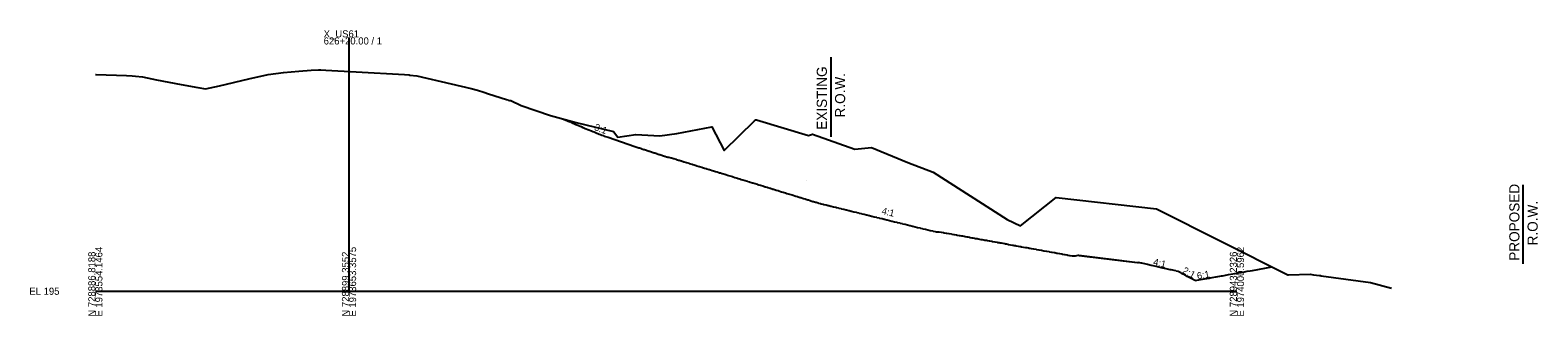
# Model space of a CAD drawing. Extents: x -26 to 630, y -39 to 9098.
# Drawn here: x -26 to 569, y 5490 to 5603 of the extents above; entities that cross this region are included whole.
import ezdxf

# ---------------------------------------------------------------- set-up
doc = ezdxf.new("R2010")
doc.units = 0
for name, color, linetype in [('CONST_DCH', 7, 'Continuous'), ('Default', 7, 'Continuous'), ('Draft_XS_Grid', 7, 'Continuous'), ('DTM_X_GROUND', 7, 'Continuous'), ('X_DTM_CONTOURS_MAJOR', 7, 'Continuous'), ('XS_CELL', 7, 'Continuous'), ('XS_P_GROUND', 7, 'Continuous'), ('XS_P_ROW', 7, 'Continuous'), ('XS_P_TX_FS_BS', 7, 'Continuous'), ('XS_X_ROW', 7, 'Continuous')]:
    doc.layers.add(name, color=color, linetype=linetype)

msp = doc.modelspace()

# ---------------------------------------------------------------- linework, layer by layer
at = {"layer": 'DTM_X_GROUND'}
msp.add_lwpolyline([(0, 5585.34), (0.34, 5585.34), (12.35, 5584.96), (14.49, 5584.89), (15.87, 5584.73), (18.56, 5584.42), (24.13, 5583.26), (33.77, 5581.44), (40.42, 5580.22), (43.38, 5579.67), (48.92, 5580.95), (60.54, 5583.64), (68.12, 5585.37), (74.21, 5586.16), (80.16, 5586.65), (85.13, 5587.07), (88.03, 5587.19), (88.84, 5587.22), (90.85, 5587.11), (102.76, 5586.44), (121.82, 5585.33), (123.66, 5585.22), (124.01, 5585.18), (126.77, 5584.86), (140.24, 5581.65), (148.09, 5579.88), (150.61, 5579.18), (153.19, 5578.38), (154.95, 5577.81), (162.05, 5575.51), (162.54, 5575.34), (162.79, 5575.25), (163.32, 5575.16), (163.78, 5575.08), (167.92, 5573.21), (179.48, 5569.21), (189.49, 5566.5), (204.19, 5562.87), (206.01, 5560.69), (213.03, 5561.75), (222.57, 5561.26), (229.25, 5562.07), (243, 5564.77), (247.82, 5555.49), (259.81, 5567.15), (260.33, 5567.54), (260.56, 5567.55), (281.09, 5561.3), (282.71, 5561.82), (299.36, 5555.96), (305.98, 5556.65), (320.29, 5550.74), (330.27, 5546.87), (359.43, 5528.31), (364.69, 5525.82), (378.69, 5536.89), (418.26, 5532.46), (470.05, 5506.4), (470.34, 5506.47), (478.82, 5506.66), (480.12, 5506.51), (482.61, 5506.17), (482.94, 5506.13), (483.15, 5506.1), (502.67, 5503.47), (510.96, 5501.18)], dxfattribs=at)
at = {"layer": 'XS_CELL'}
for p, q in [((100, 5500), (100, 5600)), ((0, 5500), (100, 5500)), ((100, 5500), (450, 5500))]:
    msp.add_line(p, q, dxfattribs=at)
at = {"layer": 'XS_P_GROUND'}
for points in [[(184.19, 5567.94), (185.14, 5567.53), (185.19, 5567.51), (186.14, 5567.11), (186.38, 5567), (187.14, 5566.68), (187.62, 5566.47), (187.74, 5566.42), (188.14, 5566.25), (188.35, 5566.16), (189.14, 5565.83), (189.39, 5565.72), (190.14, 5565.4), (190.43, 5565.28), (191.14, 5564.97), (191.47, 5564.83), (192.14, 5564.55), (192.5, 5564.4), (193.14, 5564.14), (193.53, 5563.98), (194.14, 5563.73), (194.56, 5563.56), (195.14, 5563.33), (195.58, 5563.15), (196.14, 5562.92), (196.6, 5562.73), (197.14, 5562.51), (197.62, 5562.31), (198.14, 5562.11), (198.64, 5561.9), (199.14, 5561.7), (199.65, 5561.49), (200.14, 5561.29), (200.61, 5561.15), (201.14, 5560.98), (201.6, 5560.84), (202.14, 5560.68), (212.72, 5557.04)], [(212.72, 5557.04), (213.47, 5556.79), (214.22, 5556.55), (214.48, 5556.46), (215.23, 5556.21), (215.48, 5556.13), (216.25, 5555.88), (216.49, 5555.8), (217.26, 5555.55), (217.49, 5555.48), (218.27, 5555.22), (218.49, 5555.15), (219.28, 5554.89), (219.5, 5554.82), (220.29, 5554.56), (220.5, 5554.49), (221.3, 5554.23), (221.5, 5554.16), (222.31, 5553.9), (222.51, 5553.83), (223.32, 5553.57), (223.51, 5553.51), (224.33, 5553.24), (224.51, 5553.18), (225.2, 5552.95), (225.34, 5552.91), (225.65, 5552.86), (226.09, 5552.84), (226.93, 5552.58), (227.09, 5552.53), (227.93, 5552.28), (228.09, 5552.23), (228.94, 5551.97), (229.09, 5551.92), (229.94, 5551.66), (230.09, 5551.61), (230.95, 5551.35), (231.09, 5551.31), (231.99, 5551.03), (232.09, 5551), (233.02, 5550.71), (233.09, 5550.69), (234.05, 5550.4), (234.09, 5550.38), (235.09, 5550.08), (235.09, 5550.08), (235.24, 5550.03), (235.29, 5550.02), (235.5, 5549.95), (236.09, 5549.77), (236.78, 5549.56), (237.09, 5549.46), (238.07, 5549.16), (238.09, 5549.16), (238.19, 5549.13), (239.09, 5548.85), (239.35, 5548.77), (240.09, 5548.54), (240.63, 5548.38), (240.7, 5548.36), (240.74, 5548.35), (241.09, 5548.23), (241.9, 5547.99), (242.09, 5547.93), (242.54, 5547.79), (243.09, 5547.62), (243.7, 5547.43), (244.1, 5547.31), (244.46, 5547.2), (245.1, 5547.01), (245.8, 5546.79), (246.1, 5546.7), (246.37, 5546.61), (247.1, 5546.39), (247.65, 5546.22), (248.1, 5546.08), (248.92, 5545.83), (249.1, 5545.78), (249.56, 5545.64), (250.1, 5545.47), (250.7, 5545.29), (251.1, 5545.16), (251.47, 5545.05), (252.1, 5544.86), (252.1, 5544.85), (253.1, 5544.55), (253.37, 5544.46), (254.1, 5544.24), (254.64, 5544.07), (255.1, 5543.93), (255.28, 5543.88), (256.1, 5543.63), (257.01, 5543.35), (257.1, 5543.32), (257.18, 5543.3), (257.32, 5543.25), (257.81, 5543.1), (258.1, 5543.01), (259.08, 5542.71), (259.1, 5542.71), (259.12, 5542.7), (260.1, 5542.4), (260.98, 5542.13), (261.1, 5542.09), (261.57, 5541.95), (262.1, 5541.78), (262.24, 5541.74), (263.1, 5541.48), (264.06, 5541.18), (264.1, 5541.17), (264.14, 5541.16), (264.2, 5541.14), (264.77, 5540.97), (265.1, 5540.86), (266.03, 5540.58), (266.1, 5540.56), (266.11, 5540.55), (267.1, 5540.25), (267.26, 5540.2), (268.1, 5539.94), (268.36, 5539.86), (269.1, 5539.63), (269.45, 5539.53), (270.1, 5539.33), (270.52, 5539.2), (271.1, 5539.02), (271.57, 5538.88), (272.1, 5538.71), (272.62, 5538.55), (273.1, 5538.41), (273.66, 5538.24), (274.1, 5538.1), (274.69, 5537.92), (275.1, 5537.79), (275.72, 5537.6), (276.1, 5537.48), (276.75, 5537.29), (277.1, 5537.18), (277.77, 5536.97), (278.1, 5536.87), (278.79, 5536.66), (279.1, 5536.56), (279.81, 5536.35), (280.1, 5536.26), (280.82, 5536.04), (281.1, 5535.95), (281.84, 5535.72), (282.1, 5535.64), (282.85, 5535.41), (283.1, 5535.34), (283.86, 5535.1), (284.1, 5535.03), (284.87, 5534.79), (285.1, 5534.72), (285.89, 5534.53), (286.1, 5534.48), (286.89, 5534.28), (287.1, 5534.23), (287.9, 5534.03), (288.11, 5533.99), (288.91, 5533.79), (289.11, 5533.74), (289.92, 5533.54), (290.11, 5533.5), (290.93, 5533.29), (291.11, 5533.25), (291.93, 5533.05), (292.11, 5533), (292.94, 5532.8), (293.11, 5532.76), (293.95, 5532.55), (294.11, 5532.51), (294.95, 5532.31), (295.11, 5532.27), (295.96, 5532.06), (296.11, 5532.02), (296.96, 5531.81), (297.11, 5531.78), (297.97, 5531.57), (298.11, 5531.53), (298.97, 5531.32), (299.11, 5531.29), (299.98, 5531.08), (300.11, 5531.04), (300.98, 5530.83), (301.11, 5530.8), (301.98, 5530.58), (302.11, 5530.55), (302.99, 5530.34), (303.11, 5530.31), (303.99, 5530.09), (304.11, 5530.06), (305, 5529.85), (305.11, 5529.82), (306, 5529.6), (306.11, 5529.57), (307, 5529.35), (307.11, 5529.33), (308, 5529.11), (308.11, 5529.08), (309.01, 5528.86), (309.11, 5528.84), (310.01, 5528.62), (310.11, 5528.59), (311.01, 5528.37), (311.11, 5528.35), (312.02, 5528.13), (312.11, 5528.1), (313.02, 5527.88), (313.11, 5527.86), (314.02, 5527.63), (314.11, 5527.61), (315.02, 5527.39), (315.11, 5527.37), (316.03, 5527.14), (316.11, 5527.12), (316.2, 5527.1), (317.11, 5526.88), (317.2, 5526.86), (318.11, 5526.63), (318.2, 5526.61), (319.11, 5526.39), (319.2, 5526.36), (320.11, 5526.14), (320.2, 5526.12), (321.11, 5525.9), (321.21, 5525.87), (322.11, 5525.65), (322.21, 5525.63), (323.11, 5525.41), (323.21, 5525.38), (324.11, 5525.16), (324.21, 5525.14), (325.11, 5524.92), (325.22, 5524.89), (326.11, 5524.67), (326.22, 5524.64), (327.11, 5524.42), (327.22, 5524.41), (328.11, 5524.19), (328.22, 5524.18), (329.11, 5523.96), (329.23, 5523.94), (330.11, 5523.73), (330.23, 5523.71), (331.12, 5523.49), (331.14, 5523.49), (331.34, 5523.44), (331.7, 5523.41), (331.92, 5523.41), (332.29, 5523.4), (332.52, 5523.41), (332.68, 5523.4), (333.38, 5523.28), (333.54, 5523.25), (334.39, 5523.09), (334.57, 5523.06), (335.4, 5522.91), (335.59, 5522.88), (336.42, 5522.73), (336.62, 5522.69), (337.43, 5522.55), (337.65, 5522.51), (338.44, 5522.36), (338.68, 5522.32), (339.46, 5522.18), (339.71, 5522.13), (340.47, 5522), (340.75, 5521.95), (341.49, 5521.81), (341.78, 5521.76), (342.5, 5521.63), (342.82, 5521.57), (343.51, 5521.45), (343.86, 5521.38), (344.53, 5521.26), (344.9, 5521.2), (345.54, 5521.08), (345.95, 5521.01), (346.55, 5520.9), (347, 5520.82), (347.57, 5520.72), (348.05, 5520.63), (348.58, 5520.53), (349.11, 5520.44), (349.59, 5520.35), (350.18, 5520.24), (350.61, 5520.17), (351.25, 5520.05), (351.62, 5519.98), (352.34, 5519.85), (352.63, 5519.8), (353.44, 5519.66), (353.65, 5519.62), (354.55, 5519.46), (354.66, 5519.44), (355.58, 5519.27), (355.67, 5519.25), (356.32, 5519.14), (356.69, 5519.07), (357, 5519.01), (357.7, 5518.89), (358.53, 5518.74), (358.72, 5518.7), (359.11, 5518.63), (359.73, 5518.52), (360.01, 5518.47), (360.74, 5518.34), (361.48, 5518.2), (361.76, 5518.15), (362.22, 5518.07), (362.77, 5517.97), (362.96, 5517.94), (363.78, 5517.79), (364.43, 5517.67), (364.8, 5517.61), (365.1, 5517.55), (365.81, 5517.42), (366.64, 5517.27), (366.82, 5517.24), (367.22, 5517.17), (367.84, 5517.06), (368.12, 5517.01), (368.24, 5516.98), (368.43, 5516.95), (368.85, 5516.87), (368.86, 5516.87), (369.86, 5516.69), (369.91, 5516.68), (370.88, 5516.51), (370.95, 5516.5), (371.89, 5516.33), (371.99, 5516.31), (372.91, 5516.14), (373.02, 5516.12), (373.92, 5515.96), (374.06, 5515.93), (374.93, 5515.78), (375.1, 5515.75), (375.95, 5515.59), (376.13, 5515.56), (376.96, 5515.41), (377.17, 5515.37), (377.97, 5515.23), (378.2, 5515.19), (378.99, 5515.04), (379.23, 5515), (380, 5514.86), (380.25, 5514.82), (381.01, 5514.68), (381.27, 5514.63), (382.03, 5514.5), (382.28, 5514.45), (383.04, 5514.31), (383.3, 5514.27), (384.05, 5514.13), (384.3, 5514.09), (384.99, 5513.96), (386.18, 5513.9), (386.37, 5513.91), (387.38, 5514.14), (387.59, 5514.15), (387.92, 5514.11), (388.64, 5514.02), (388.99, 5513.98), (389.69, 5513.9), (390.06, 5513.85), (390.75, 5513.77), (391.13, 5513.72), (391.8, 5513.64), (392.2, 5513.59), (392.86, 5513.51), (393.28, 5513.46), (393.91, 5513.39), (394.35, 5513.33), (394.96, 5513.26), (395.43, 5513.2), (396.02, 5513.13), (396.51, 5513.07), (397.07, 5513), (397.59, 5512.94), (398.12, 5512.88), (398.67, 5512.81), (399.18, 5512.75), (399.75, 5512.68), (400.23, 5512.62), (400.83, 5512.55), (401.28, 5512.5), (401.92, 5512.42), (402.34, 5512.37), (403.01, 5512.29), (403.39, 5512.24), (404.1, 5512.15), (404.44, 5512.11), (405.2, 5512.02), (405.5, 5511.99), (406.3, 5511.89), (406.55, 5511.86), (407.4, 5511.75), (407.6, 5511.73), (408.51, 5511.62), (408.66, 5511.6), (409.62, 5511.49), (409.71, 5511.48), (410.74, 5511.35), (410.77, 5511.35), (411.18, 5511.3)], [(426.81, 5507.79), (426.06, 5507.96), (425.95, 5507.98), (424.09, 5508.4), (423.7, 5508.49), (422.13, 5508.84), (421.45, 5508.99), (420.16, 5509.28), (419.2, 5509.5), (418.2, 5509.72), (416.96, 5510), (416.23, 5510.16), (414.71, 5510.51), (414.26, 5510.6), (412.46, 5511.01), (412.3, 5511.05), (411.18, 5511.3)], [(433.51, 5504.18), (434.94, 5504.43), (435.66, 5504.56), (437.19, 5504.84), (439.04, 5505.17), (439.43, 5505.24), (440.21, 5505.38), (441.68, 5505.64), (441.82, 5505.66), (443.93, 5506.04), (444.28, 5506.1), (446.18, 5506.44), (446.73, 5506.54), (448.42, 5506.84), (449.18, 5506.98), (450.67, 5507.24), (451.63, 5507.41), (452.92, 5507.64), (454.08, 5507.85), (455.17, 5508.04), (456.09, 5508.21), (463.74, 5509.57)], [(433.51, 5504.18), (432.9, 5504.51), (432.69, 5504.62), (431.21, 5505.42), (430.44, 5505.83), (429.53, 5506.32), (428.19, 5507.04), (427.85, 5507.23), (426.81, 5507.79)]]:
    msp.add_lwpolyline(points, dxfattribs=at)
at = {"layer": 'XS_P_ROW'}
msp.add_line((562.73, 5541.85), (562.73, 5510.84), dxfattribs=at)
at = {"layer": 'XS_X_ROW'}
msp.add_line((290, 5560.81), (290, 5592.16), dxfattribs=at)

# ---------------------------------------------------------------- texts
at = {"layer": 'CONST_DCH'}
msp.add_text('X', height=0.001, dxfattribs=at).set_placement((433.51, 5504.18))
at = {"layer": 'Default'}
for height, p in [(0.12, (204.52, 5562.37)), (0.12, (208.63, 5561.03)), (0.12, (218.43, 5557.82)), (0.001, (426.81, 5507.79)), (0.001, (433.51, 5504.18))]:
    msp.add_text('X', height=height, dxfattribs=at).set_placement(p)
at = {"layer": 'Draft_XS_Grid'}
msp.add_text('-', height=0.0001, dxfattribs=at).set_placement((0, 5500))
at = {"layer": 'X_DTM_CONTOURS_MAJOR'}
msp.add_text('X', height=0.12, dxfattribs=at).set_placement((280.12, 5543.58))
at = {"layer": 'XS_CELL'}
for s, p in [('X_US61', (90, 5600)), ('626+20.00 / 1', (90, 5597.2)), ('EL 195', (-26, 5498.6))]:
    msp.add_text(s, height=2.8, dxfattribs=at).set_placement(p)
for s, p in [('N 728886.8188', (0, 5490)), ('E 1973554.1464', (2.8, 5490)), ('N 728899.3552', (100, 5490)), ('E 1973653.3575', (102.8, 5490)), ('N 728943.2326', (450, 5490)), ('E 1974000.5962', (452.8, 5490))]:
    msp.add_text(s, height=2.8, rotation=90, dxfattribs=at).set_placement(p)
at = {"layer": 'XS_P_ROW'}
for s, p in [('EXISTING', (288.37, 5563.6)), ('R.O.W.', (295.57, 5568.44)), ('PROPOSED', (561.36, 5511.99)), ('R.O.W.', (568.56, 5518.06))]:
    msp.add_text(s, height=4, rotation=90, dxfattribs=at).set_placement(p)
at = {"layer": 'XS_P_TX_FS_BS'}
for s, rotation, p in [('3:1', 339.08877, (196.42, 5563.59)), ('4:1', 347.02166, (309.78, 5530.44)), ('4:1', 347.33938, (416.82, 5510.34)), ('2:1', 331.71565, (428.28, 5507.34)), ('6:1', 10.1138, (434.49, 5504.66))]:
    msp.add_text(s, height=2.7, rotation=rotation, dxfattribs=at).set_placement(p)

doc.saveas('drawing.dxf')
